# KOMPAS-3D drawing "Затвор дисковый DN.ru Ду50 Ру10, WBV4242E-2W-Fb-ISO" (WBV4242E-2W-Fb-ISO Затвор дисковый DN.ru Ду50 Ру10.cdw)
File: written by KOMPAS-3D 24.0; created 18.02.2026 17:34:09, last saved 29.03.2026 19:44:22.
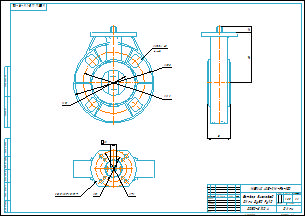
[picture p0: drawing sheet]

Document properties: Автор: R2D2; Форматы листов документа: A2; Полное имя файла: WBV4242E-2W-Fb-ISO Затвор дисковый DN.ru Ду50 Ру10.m3d; Масса: 0.85; Наименование: Затвор дисковый DN.ru Ду50 Ру10; Количество листов документа: 1; Примечание: D050-81204

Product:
- Part/product: Затвор дисковый DN.ru Ду50 Ру10  | designation WBV4242E-2W-Fb-ISO
    Масса: 0.85
    Раздел спецификации: Прочие изделия
    Форматы листов документа: A2
    Примечание: D050-81204

Views: Вид 1, Спереди, Проекционный вид 2
Referenced files in E:\Работа\Зайцев\WBV4242E-2W-Fb-ISO Затвор дисковый DN.ru Ду50-200 Ру10\DN50\: WBV4242E-2W-Fb-ISO Затвор дисковый DN.ru Ду50 Ру10.m3d
Referenced files in E:\Работа\Зайцев\Для компаса\: чертеж DN.ru А3.cdt
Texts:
  WBV4242E-2W-Fb-ISO
  чертеж DN.ru А3.cdt
  Затвор дисковый
  DN.ru Ду50 Ру10
  Затвор дисковый DN.ru Ду50 Ру10
  WBV4242E-2W-Fb-ISO Затвор дисковый DN.ru Ду50 Ру10
Dimensions and other numbers on the sheet: 0; 3; 2; 4; 158; 121; 4 отв.; 50; 98; 45; 13; 1:1; 1; 0,85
